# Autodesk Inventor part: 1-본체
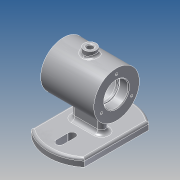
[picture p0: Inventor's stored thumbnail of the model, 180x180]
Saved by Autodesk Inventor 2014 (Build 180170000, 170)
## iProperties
Created: 2017-12
Part Number: 1-본체
Material: 알루미늄 6061
Document SubType Name: Modeling
Designer: kb542-16
Density: 2.71 g/cm^3
Appearance: 알루미늄 - 평지
Mass: 467.721 g
Surface Area: 486.578 cm^2
Volume: 172.591 cm^3
Author: kb542-16
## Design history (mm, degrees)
sketch "스케치1"
  geometry: L1 (0, 55)-(0, -55); L2 (-35, 42.426)-(-35, -42.426); L3 (35, 42.426)-(35, -42.426); A1 r 55 centre (0, 0) between (0, 55) and (0, -55); 2 further points
  constraints: 6 end point, 6 point on circle, 2 coincident, 2 parallel, 1 centre point, 1 midpoint, 1 vertical
  dimensions: "d0" = 55 radius of A1; "d1" = 35 distance from line of L2 point (0, 0); "d2" = 70 distance between parallel lines of L3 L2
extrude "돌출1" new body sketch "스케치1" distance "d3" = 10; taper "d4" = 0 deg
sketch "스케치2"
  geometry: L1 (-35, 42.426)-(-35, -42.426) reference; L2 (0, 40)-(0, 24); L3 (-5, 40)-(-5, 24); L4 (5, 24)-(5, 40); A1 r 55 centre (0, 0) between (-35, -42.426) and (35, -42.426) reference; A2 r 5 centre (0, 40) between (5, 40) and (-5, 40); A3 r 5 centre (0, 24) between (-5, 24) and (5, 24); 1 further point
  constraints: 8 end point, 4 point on circle, 4 tangent, 2 centre point, 2 parallel, 1 midpoint, 1 vertical alignment
  dimensions: "d5" = 16 distance of L2.start L2.end; "d6" = 5 radius of A2; "d7" = 24 distance of A1.centre L2.end
extrude "돌출2" cut sketch "스케치2" stored distance "d8" = 10; taper "d9" = 0 deg
sketch "스케치3"
  geometry: L1 (-35, 92)-(35, 92); L2 (35, 92)-(35, 62); L3 (35, 62)-(-35, 62); L4 (-35, 62)-(-35, 92); L5 (35, 0)-(-35, 0) reference; 3 further points
  constraints: 8 end point, 2 midpoint, 2 parallel, 1 horizontal, 1 perpendicular, 1 vertical alignment
  dimensions: "d10" = 62 distance between parallel lines of L5 L3; "d11" = 70 distance of L1.start L1.end; "d12" = 60 diameter of L1 L3
revolve "회전1" sketch "스케치3" stored, may be unused: angle "d13" = 90 deg
sketch "스케치4"
  geometry: L1 (35, 32)-(35, 92) reference; L2 (-35, 32)-(-35, 92) reference; L3 (-35, 92)-(35, 92) reference; L4 (-35, 32)-(35, 32) reference; L5 (-35, 78)-(-23.3, 78); L6 (-23, 77.7)-(-23, 76); L7 (-23, 76)-(-20.3, 76); L8 (-20, 76.3)-(-20, 84); L9 (-17, 87)-(17, 87); L10 (20, 84)-(20, 76.3); L11 (20.3, 76)-(23, 76); L12 (23, 76)-(23, 77.7); L13 (23.3, 78)-(35, 78); L14 (35, 78)-(35, 62); L15 (-35, 62)-(-35, 78); L16 (-35, 62)-(35, 62); L17 (35, 0)-(-35, 0) reference; L18 (-5, 10)-(5, 10) reference; L19 (20.3, 76)-(20, 76); L20 (20, 76)-(20, 76.3); L21 (-20.3, 76)-(-20, 76); L22 (-20, 76)-(-20, 76.3); A1 r 3 centre (17, 84) between (20, 84) and (17, 87); A2 r 3 centre (-17, 84) between (-17, 87) and (-20, 84); A3 r 0.3 centre (-23.3, 77.7) between (-23, 77.7) and (-23.3, 78); A4 r 0.3 centre (23.3, 77.7) between (23.3, 78) and (23, 77.7); 8 further points
  constraints: 32 end point, 10 point on line, 8 parallel, 8 point on circle, 8 tangent, 6 perpendicular, 4 centre point, 3 midpoint, 3 vertical alignment, 2 equal radius, 1 collinear
  dimensions: "d14" = 62 distance between parallel lines of L17 L16; "d15" = 32 diameter of L5 L16; "d16" = 28 diameter of L7 L16; "d17" = 50 diameter of L9 L16; "d18" = 28 diameter of L11 L16; "d19" = 32 diameter of L13 L16; "d22" = 40 distance of point (-20, 87) point (20, 87); "d23" = 3 radius of A1; "d65" = 3 distance between parallel lines of L10 L12; "d66" = 3 distance between parallel lines of L6 L8; "d67" = 0.3 radius of A3
revolve "회전2" sketch "스케치4" stored, may be unused: angle "d25" = 90 deg
sketch "스케치5"
  geometry: L1 (35, -42.426)-(35, 42.426) reference; L2 (-15, 0)-(15, 0); L3 (-15, -5)-(15, -5); L4 (15, 5)-(-15, 5); A1 r 55 centre (0, 0) between (-35, -42.426) and (35, -42.426) reference; A2 r 5 centre (-15, 0) between (-15, 5) and (-15, -5); A3 r 5 centre (15, 0) between (15, -5) and (15, 5); 1 further point
  constraints: 8 end point, 4 point on circle, 4 tangent, 2 centre point, 1 coincident, 1 midpoint, 1 parallel, 1 perpendicular
  dimensions: "d26" = 30 distance of L2.start L2.end; "d27" = 5 radius of A3
extrude "돌출3" join sketch "스케치5" stored distance "d28" = 0; taper "d29" = 0 deg
node "작업 평면1"
sketch "스케치6"
  geometry: C1 r 8 at (0, 0); 1 further point
  constraints: 1 centre point, 1 coincident
  dimensions: "d31" = 16 diameter of C1
extrude "돌출4" join sketch "스케치6" stored distance "d32" = 10; taper "d33" = 0 deg
sketch "스케치8"
  geometry: C1 r 8 at (0, 0) reference; C2 r 4 at (0, 0)
  constraints: 1 centre point, 1 coincident
  dimensions: "d41" = 8 diameter of C2
extrude "돌출5" cut sketch "스케치8" distance "d42" = 20; taper "d43" = 0 deg
sketch "스케치9" dims "d44" = 23
  geometry: L1 (0, 0)-(23, 0); C1 r 30 at (0, 0) reference; 1 further point
  constraints: 2 end point, 1 coincident, 1 horizontal alignment, 2 other
hole "구멍2" sketch "스케치9" at (23, 0) diameter "d45" = 3.242; stored, may be unused: countersink angle "d49" = 90 deg, drill point angle "d51" = 118 deg; dims "d46" = 8, "d47" = 4, "d48" = 2, "d50" = 10
node "작업 평면3"
sketch "스케치11"
  geometry: L1 (35, -62)-(-35, -62) reference; L2 (-35, 30)-(35, 30) reference; 2 further points
  constraints: 1 vertical alignment, 1 other
  dimensions: "d56" = 30 distance from line of point (0, 0) L2
feature "엠보싱1" sketch "스케치11" dims "d57" = 0.5, "d58" = 0
fillet "모깎기1" dims "d59" = 5
fillet "모깎기2" dims "d60" = 3
fillet "모깎기3" dims "d61" = 3
chamfer "모따기1" distance "d62" = 1; stored, may be unused: second distance "d63" = 2, angle "d64" = 45 deg
node "솔리드1"
mirror "대칭1"
pattern_circular "원형 패턴1" dims angle "d53" = 360 deg
mirror "대칭2"
node "투영된 루프1"
other parameters: "d30" = 99
